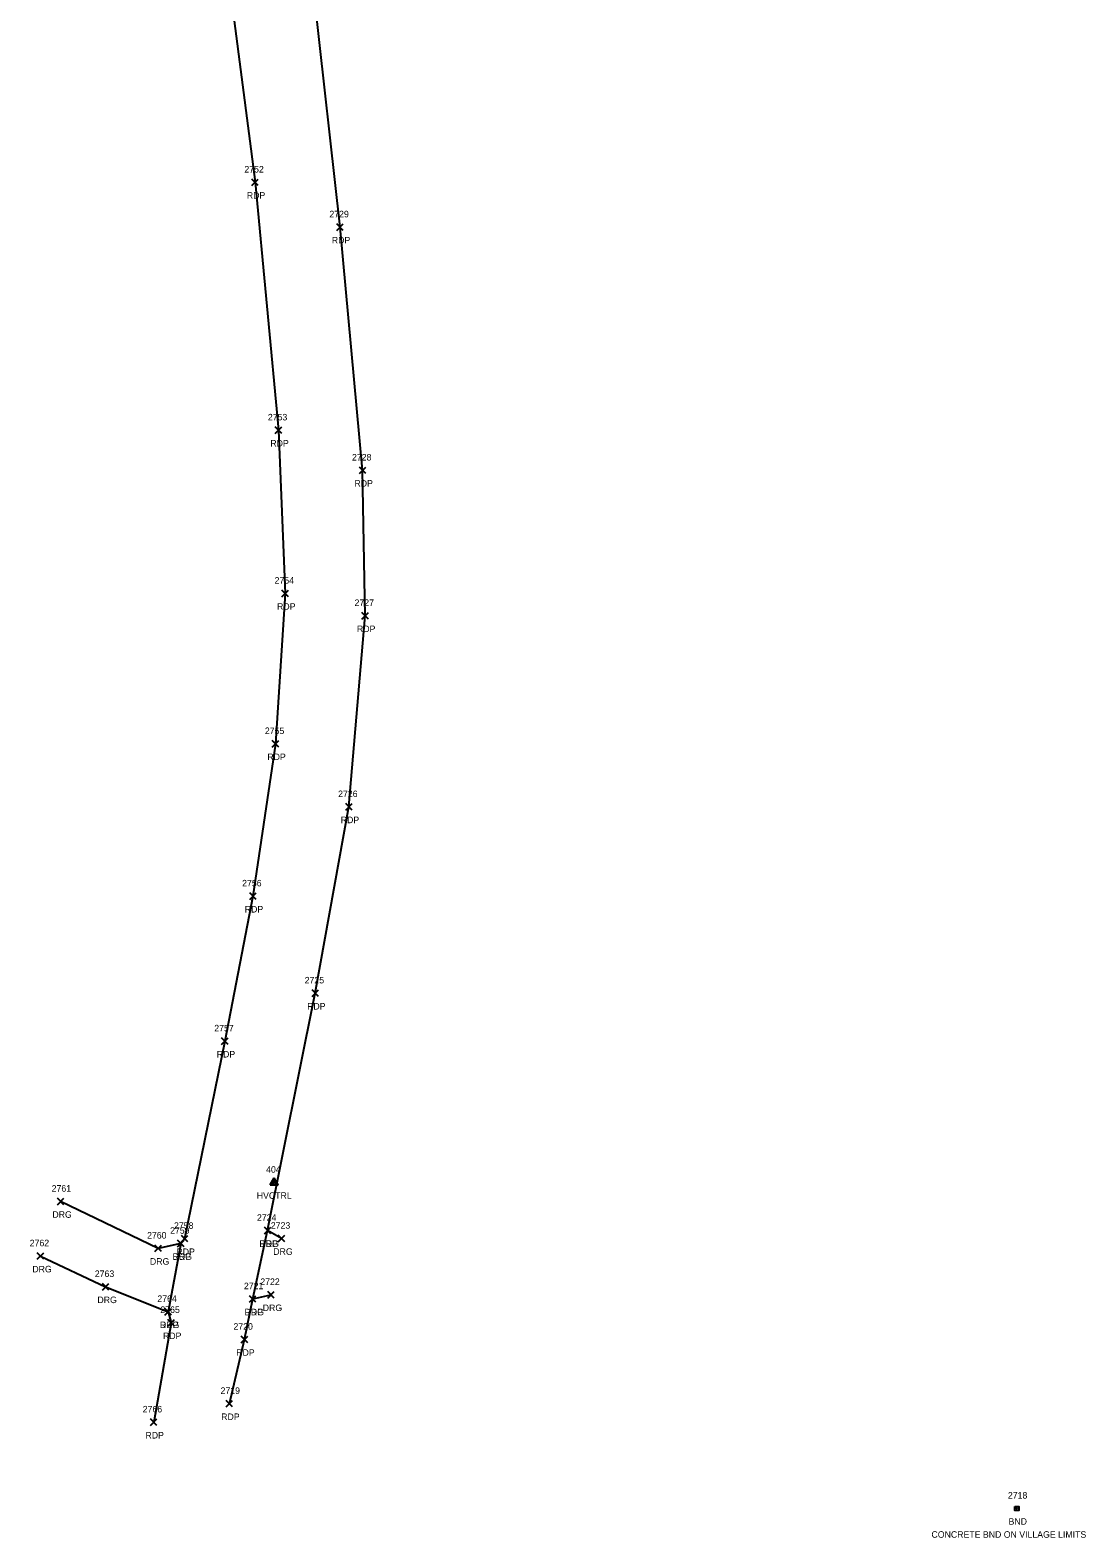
# Model space of a CAD drawing. Extents: x 1767353 to 1772625, y 740790 to 747702.
# Drawn here: x 1772126.2 to 1772449.6, y 744744.4 to 745206.4 of the extents above; entities that cross this region are included whole.
import ezdxf

# ---------------------------------------------------------------- set-up
doc = ezdxf.new("R2010")
doc.units = 0
for name, color, linetype in [('C_A', 7, 'Continuous'), ('C_I', 7, 'Continuous'), ('CPSM', 7, 'Continuous'), ('Level 18', 7, 'Continuous'), ('M_A', 7, 'Continuous'), ('M_C', 7, 'Continuous'), ('M_I', 7, 'Continuous'), ('P_A', 7, 'Continuous'), ('P_I', 7, 'Continuous'), ('P_TIC', 7, 'Continuous'), ('PET', 7, 'Continuous'), ('R_A', 7, 'Continuous'), ('R_I', 7, 'Continuous'), ('R_TIC', 7, 'Continuous'), ('RDG', 7, 'Continuous')]:
    doc.layers.add(name, color=color, linetype=linetype)

msp = doc.modelspace()

# ---------------------------------------------------------------- linework, layer by layer
at = {"layer": 'CPSM'}
for p, q in [((1772199.66, 744852.57), (1772200.91, 744854.73)), ((1772199.66, 744852.57), (1772200.91, 744854.73)), ((1772199.66, 744852.57), (1772200.91, 744854.73)), ((1772202.16, 744852.57), (1772200.91, 744854.73)), ((1772200.91, 744853.29), (1772200.91, 744854.73)), ((1772202.16, 744852.57), (1772200.91, 744854.73)), ((1772200.91, 744853.29), (1772200.91, 744854.73)), ((1772202.16, 744852.57), (1772200.91, 744854.73)), ((1772200.91, 744853.29), (1772200.91, 744854.73)), ((1772199.66, 744852.57), (1772200.91, 744853.29)), ((1772199.66, 744852.57), (1772200.91, 744853.29)), ((1772199.66, 744852.57), (1772200.91, 744853.29)), ((1772199.66, 744852.57), (1772202.16, 744852.57)), ((1772199.66, 744852.57), (1772202.16, 744852.57)), ((1772199.66, 744852.57), (1772202.16, 744852.57)), ((1772200.91, 744853.29), (1772200.91, 744853.29)), ((1772200.91, 744853.29), (1772202.16, 744852.57)), ((1772200.91, 744853.29), (1772200.91, 744853.29)), ((1772200.91, 744853.29), (1772202.16, 744852.57)), ((1772200.91, 744853.29), (1772200.91, 744853.29)), ((1772200.91, 744853.29), (1772202.16, 744852.57))]:
    msp.add_line(p, q, dxfattribs=at)
at = {"layer": 'Level 18'}
msp.add_lwpolyline([(1772427.75, 744754.07), (1772429, 744754.07), (1772429, 744752.82), (1772427.75, 744752.82)], close=True, dxfattribs=at)
msp.add_circle((1772428.38, 744753.45), 0.0833, dxfattribs=at)
at = {"layer": 'P_TIC'}
for points in [[(1772194.06, 745158.73), (1772196.06, 745160.73)], [(1772196.06, 745158.73), (1772194.06, 745160.73)], [(1772220.11, 745145), (1772222.11, 745147)], [(1772222.11, 745145), (1772220.11, 745147)], [(1772201.26, 745082.78), (1772203.26, 745084.78)], [(1772203.26, 745082.78), (1772201.26, 745084.78)], [(1772227.03, 745070.5), (1772229.03, 745072.5)], [(1772229.03, 745070.5), (1772227.03, 745072.5)], [(1772203.32, 745032.77), (1772205.32, 745034.77)], [(1772205.32, 745032.77), (1772203.32, 745034.77)], [(1772227.81, 745025.92), (1772229.81, 745027.92)], [(1772229.81, 745025.92), (1772227.81, 745027.92)], [(1772200.34, 744986.69), (1772202.34, 744988.69)], [(1772202.34, 744986.69), (1772200.34, 744988.69)], [(1772222.83, 744967.38), (1772224.83, 744969.38)], [(1772224.83, 744967.38), (1772222.83, 744969.38)], [(1772193.43, 744940.01), (1772195.43, 744942.01)], [(1772195.43, 744940.01), (1772193.43, 744942.01)], [(1772212.53, 744910.28), (1772214.53, 744912.28)], [(1772214.53, 744910.28), (1772212.53, 744912.28)], [(1772184.84, 744895.59), (1772186.84, 744897.59)], [(1772186.84, 744895.59), (1772184.84, 744897.59)], [(1772171.31, 744833.59), (1772173.31, 744835.59)], [(1772173.31, 744833.59), (1772171.31, 744835.59)], [(1772172.51, 744835.08), (1772174.51, 744837.08)], [(1772174.51, 744835.08), (1772172.51, 744837.08)], [(1772197.92, 744837.56), (1772199.92, 744839.56)], [(1772199.92, 744837.56), (1772197.92, 744839.56)], [(1772193.36, 744816.6), (1772195.36, 744818.6)], [(1772195.36, 744816.6), (1772193.36, 744818.6)], [(1772167.45, 744812.69), (1772169.45, 744814.69)], [(1772169.45, 744812.69), (1772167.45, 744814.69)], [(1772168.38, 744809.32), (1772170.38, 744811.32)], [(1772170.38, 744809.32), (1772168.38, 744811.32)], [(1772190.81, 744804.19), (1772192.81, 744806.19)], [(1772192.81, 744804.19), (1772190.81, 744806.19)], [(1772186.21, 744784.53), (1772188.21, 744786.53)], [(1772188.21, 744784.53), (1772186.21, 744786.53)], [(1772163.02, 744778.85), (1772165.02, 744780.85)], [(1772165.02, 744778.85), (1772163.02, 744780.85)]]:
    msp.add_lwpolyline(points, dxfattribs=at)
at = {"layer": 'PET'}
for points in [[(1772140.5, 746182.43), (1772136.6, 746134.25), (1772132.65, 746062.39), (1772130.5, 745987.91), (1772129.51, 745857.83), (1772129.48, 745709.99), (1772132.25, 745655.35), (1772144.74, 745526.19), (1772153.94, 745453.17), (1772156.72, 745435.01), (1772160.6, 745405.99), (1772174.99, 745306.33), (1772184.47, 745241.47), (1772195.06, 745159.73), (1772202.26, 745083.78), (1772204.32, 745033.77), (1772201.34, 744987.69), (1772194.43, 744941.01), (1772185.84, 744896.59), (1772173.51, 744836.08), (1772172.31, 744834.59), (1772168.45, 744813.69), (1772169.38, 744810.32), (1772164.02, 744779.85)], [(1772187.21, 744785.53), (1772191.81, 744805.19), (1772194.36, 744817.6), (1772198.92, 744838.56), (1772213.53, 744911.28), (1772223.83, 744968.38), (1772228.81, 745026.92), (1772228.03, 745071.5), (1772221.11, 745146), (1772213.24, 745216.37), (1772203.04, 745284.67), (1772194.18, 745344.74), (1772183.97, 745410.43), (1772175.99, 745473.54), (1772167.17, 745549.02), (1772164.13, 745576.45)]]:
    msp.add_lwpolyline(points, dxfattribs=at)
at = {"layer": 'R_TIC'}
for points in [[(1772134.51, 744846.48), (1772136.51, 744848.48)], [(1772136.51, 744846.48), (1772134.51, 744848.48)], [(1772171.31, 744833.59), (1772173.31, 744835.59)], [(1772173.31, 744833.59), (1772171.31, 744835.59)], [(1772197.92, 744837.56), (1772199.92, 744839.56)], [(1772199.92, 744837.56), (1772197.92, 744839.56)], [(1772202.17, 744835.13), (1772204.17, 744837.13)], [(1772204.17, 744835.13), (1772202.17, 744837.13)], [(1772128.36, 744829.76), (1772130.36, 744831.76)], [(1772130.36, 744829.76), (1772128.36, 744831.76)], [(1772164.4, 744832.11), (1772166.4, 744834.11)], [(1772166.4, 744832.11), (1772164.4, 744834.11)], [(1772148.3, 744820.34), (1772150.3, 744822.34)], [(1772150.3, 744820.34), (1772148.3, 744822.34)], [(1772193.36, 744816.6), (1772195.36, 744818.6)], [(1772195.36, 744816.6), (1772193.36, 744818.6)], [(1772198.94, 744817.9), (1772200.94, 744819.9)], [(1772200.94, 744817.9), (1772198.94, 744819.9)], [(1772167.45, 744812.69), (1772169.45, 744814.69)], [(1772169.45, 744812.69), (1772167.45, 744814.69)]]:
    msp.add_lwpolyline(points, dxfattribs=at)
at = {"layer": 'RDG'}
for points in [[(1772172.31, 744834.59), (1772165.4, 744833.11), (1772135.51, 744847.48)], [(1772203.17, 744836.13), (1772198.92, 744838.56)], [(1772129.36, 744830.76), (1772149.3, 744821.34), (1772168.45, 744813.69)], [(1772194.36, 744817.6), (1772199.94, 744818.9)]]:
    msp.add_lwpolyline(points, dxfattribs=at)

# ---------------------------------------------------------------- texts
at = {"layer": 'C_A'}
msp.add_text('HVCTRL', height=2, dxfattribs=at).set_placement((1772195.6, 744848.29))
msp.add_text('HVCTRL', height=2, dxfattribs=at).set_placement((1772195.6, 744848.29))
msp.add_text('HVCTRL', height=2, dxfattribs=at).set_placement((1772195.6, 744848.29))
at = {"layer": 'C_I'}
msp.add_text('404', height=2, dxfattribs=at).set_placement((1772198.47, 744856.29))
msp.add_text('404', height=2, dxfattribs=at).set_placement((1772198.47, 744856.29))
msp.add_text('404', height=2, dxfattribs=at).set_placement((1772198.47, 744856.29))
at = {"layer": 'M_A'}
msp.add_text('BND', height=2, dxfattribs=at).set_placement((1772425.87, 744748.45))
at = {"layer": 'M_C'}
msp.add_text('CONCRETE BND ON VILLAGE LIMITS', height=2, dxfattribs=at).set_placement((1772402.27, 744744.45))
at = {"layer": 'M_I'}
msp.add_text('2718', height=2, dxfattribs=at).set_placement((1772425.68, 744756.45))
at = {"layer": 'P_A'}
for p in [(1772192.55, 745154.73), (1772218.59, 745141), (1772199.75, 745078.78), (1772225.52, 745066.5), (1772201.81, 745028.77), (1772226.29, 745021.92), (1772198.83, 744982.69), (1772221.32, 744963.38), (1772191.92, 744936.01), (1772211.02, 744906.28), (1772183.33, 744891.59), (1772196.41, 744833.56), (1772169.8, 744829.59), (1772171, 744831.08), (1772191.85, 744812.6), (1772165.93, 744808.69), (1772166.87, 744805.32), (1772189.3, 744800.19), (1772184.7, 744780.53), (1772161.51, 744774.85)]:
    msp.add_text('RDP', height=2, dxfattribs=at).set_placement(p)
at = {"layer": 'P_I'}
for s, p in [('2752', (1772191.8, 745162.73)), ('2729', (1772217.84, 745149)), ('2753', (1772199, 745086.78)), ('2728', (1772224.77, 745074.5)), ('2754', (1772201.06, 745036.77)), ('2727', (1772225.55, 745029.92)), ('2755', (1772198.08, 744990.69)), ('2726', (1772220.52, 744971.38)), ('2756', (1772191.12, 744944.01)), ('2725', (1772210.27, 744914.28)), ('2757', (1772182.58, 744899.59)), ('2758', (1772170.25, 744839.08)), ('2724', (1772195.66, 744841.56)), ('2759', (1772169.05, 744837.59)), ('2721', (1772191.66, 744820.6)), ('2764', (1772165.14, 744816.69)), ('2765', (1772166.07, 744813.32)), ('2720', (1772188.46, 744808.19)), ('2719', (1772184.51, 744788.53)), ('2766', (1772160.66, 744782.85))]:
    msp.add_text(s, height=2, dxfattribs=at).set_placement(p)
at = {"layer": 'R_A'}
for p in [(1772132.99, 744842.48), (1772196.41, 744833.56), (1772169.8, 744829.59), (1772200.66, 744831.13), (1772126.85, 744825.76), (1772162.88, 744828.11), (1772146.79, 744816.34), (1772191.85, 744812.6), (1772197.43, 744813.9), (1772165.93, 744808.69)]:
    msp.add_text('DRG', height=2, dxfattribs=at).set_placement(p)
at = {"layer": 'R_I'}
for s, p in [('2761', (1772132.77, 744850.48)), ('2724', (1772195.66, 744841.56)), ('2723', (1772199.91, 744839.13)), ('2762', (1772126.05, 744833.76)), ('2760', (1772162, 744836.11)), ('2759', (1772169.05, 744837.59)), ('2763', (1772145.99, 744824.34)), ('2721', (1772191.66, 744820.6)), ('2722', (1772196.68, 744821.9)), ('2764', (1772165.14, 744816.69))]:
    msp.add_text(s, height=2, dxfattribs=at).set_placement(p)

doc.saveas('drawing.dxf')
